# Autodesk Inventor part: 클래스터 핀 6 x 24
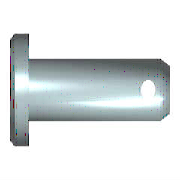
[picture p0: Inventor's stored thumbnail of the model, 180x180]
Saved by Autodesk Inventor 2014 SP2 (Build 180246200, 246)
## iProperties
IsCustomPart: 1
Created: 2012-02
Part Number: 클래스터 핀 6 x 24
Material: 강철
Description: 머리가 있는 클레비스 핀
Document SubType Name: Modeling
Standard: ISO 2341
Designer: mduedu
Standard Revision: Second edition 1986-11-01
Standards Organization: ISO
Language: ko-KR
Size Designation: B - 6 x 24
Categories: <MemberInstance><Categories><Category DisplayName="조임쇠" InternalName="e4da775c-781d-43d5-af7c-5136215cf5a6" Mnemonic="FSTN"><Category DisplayName="핀" InternalNa
Density: 7.85 g/cm^3
Appearance: 주황색
Author: mduedu
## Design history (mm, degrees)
sketch "스케치1"
  geometry: L1 (-2, 0)-(-2, 5); L2 (-2, 5)-(0, 5); L3 (0, 5)-(0, 3); L4 (0, 3)-(24, 3); L5 (24, 3)-(24, 0); L6 (-2, 0)-(24, 0); L7 (-4, 0)-(17, 0) reference; L8 (0, -0.98)-(0, 3.08) reference; C1 r 0.8 at (20.8, 0)
  constraints: 12 end point, 3 parallel, 2 collinear, 2 perpendicular, 1 centre point, 1 point on line, 1 vertical
  dimensions: "d0" = 6 diameter of L4 L6 (= NND); "d1" = 10 diameter of L2 L6 (= KOD); "d2" = 2 distance of L1.end L2.end (= KOH); "d3" = 24 distance of L3.end L4.end (= NLG); "d5" = 3.2 distance from line of L5 C1.centre (= DIST); "d6" = 1.6 diameter of C1 (= BOR)
revolve "본체" stored, may be unused: angle "d4" = 90 deg
extrude "구멍" cut sketch "스케치1" stored distance "d7" = 6 (= NND); taper "d8" = 0 deg
workaxis "Work Axis1"
workplane "Work Plane1"
body "Solid1"
chamfer "모따기1" distance "d9" = 1 (= PHH2); stored, may be unused: angle "d10" = 45 deg (= FAWI2), second distance "d16" = 1 (= PHH2)
chamfer "모따기2" distance "d11" = 2 (= PHH1); stored, may be unused: angle "d12" = 30 deg (= FAWI1), second distance "d17" = 2 (= PHH1)
other parameters: "PHH1" = 2 [user parameter; used in 2 equation terms], "PHH2" = 1 [user parameter; used in 2 equation terms], "KOD" = 10 [user parameter; used in 1 equation term], "KOH" = 2 [user parameter; used in 1 equation term], "NND" = 6 [user parameter; used in 2 equation terms], "FAWI1" = 30 deg [user parameter; used in 1 equation term], "FAWI2" = 45 deg [user parameter; used in 1 equation term], "DIST" = 3.2 [user parameter; used in 1 equation term], "BOR" = 1.6 [user parameter; used in 1 equation term], "NLG" = 24 [user parameter; used in 1 equation term], "d13" = 0, "d14" = 0, "d27" = 0, "d28" = 0, "d29" = 0, "d30" = 0, "d31" = 0
